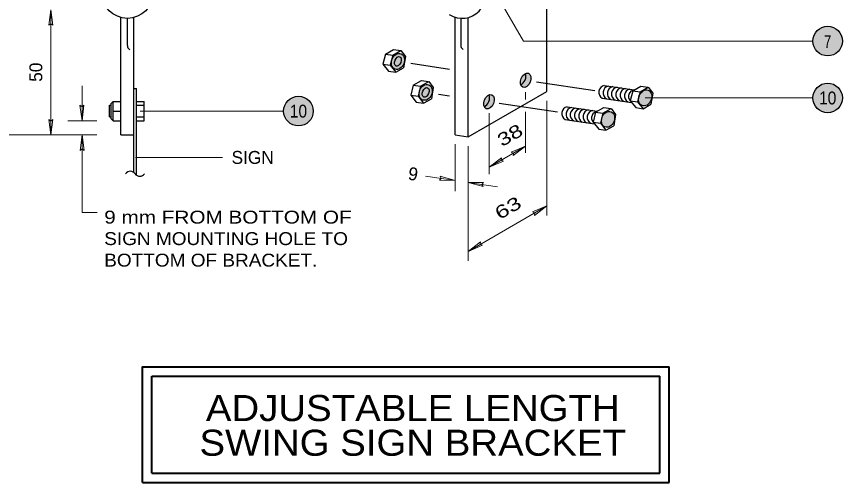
# Model space of a CAD drawing. Extents: x 312583 to 312853, y 144376 to 144586.
# Drawn here: x 312632.09 to 312680.07, y 144527.1 to 144554.18 of the extents above; entities that cross this region are included whole.
import ezdxf
from ezdxf.enums import TextEntityAlignment as Align

# ---------------------------------------------------------------- set-up
doc = ezdxf.new("R2010")
doc.units = 0
doc.header["$LTSCALE"] = 0.3
doc.layers.add('1', color=7, linetype='Continuous', lineweight=25)
doc.layers.add('2', color=7, linetype='Continuous', lineweight=13)

msp = doc.modelspace()

# ---------------------------------------------------------------- hatches: boundary and pattern name
at = {"layer": '1'}
h = msp.add_hatch(color=256, dxfattribs=at)
edge = h.paths.add_edge_path()
edge.add_ellipse((312654.2501, 144551.577), major_axis=(0.1805, 0.4441), ratio=0.761491, start_angle=0, end_angle=360)
h = msp.add_hatch(color=256, dxfattribs=at)
edge = h.paths.add_edge_path()
edge.add_ellipse((312654.2501, 144551.577), major_axis=(0.11, 0.2708), ratio=0.6087617, start_angle=0, end_angle=360)
h = msp.add_hatch(color=256, dxfattribs=at)
edge = h.paths.add_edge_path()
edge.add_ellipse((312661.6671, 144550.479), major_axis=(0.1639, 0.4034), ratio=0.649846, start_angle=0, end_angle=360)
h = msp.add_hatch(color=256, dxfattribs=at)
edge = h.paths.add_edge_path()
edge.add_ellipse((312655.8617, 144549.7761), major_axis=(0.1805, 0.4441), ratio=0.761491, start_angle=0, end_angle=360)
h = msp.add_hatch(color=256, dxfattribs=at)
edge = h.paths.add_edge_path()
edge.add_ellipse((312655.8617, 144549.7761), major_axis=(0.11, 0.2708), ratio=0.6087617, start_angle=0, end_angle=360)
h = msp.add_hatch(color=256, dxfattribs=at)
edge = h.paths.add_edge_path()
edge.add_ellipse((312668.6088, 144549.4512), major_axis=(0.1805, 0.4441), ratio=0.761491, start_angle=0, end_angle=360)
h = msp.add_hatch(color=256, dxfattribs=at)
edge = h.paths.add_edge_path()
edge.add_ellipse((312659.5421, 144549.2312), major_axis=(0.1639, 0.4034), ratio=0.649846, start_angle=0, end_angle=360)
h = msp.add_hatch(color=256, dxfattribs=at)
edge = h.paths.add_edge_path()
edge.add_ellipse((312666.4551, 144548.2077), major_axis=(0.1805, 0.4441), ratio=0.761491, start_angle=0, end_angle=360)
at = {"layer": '2'}
for points in [[(312680.0731, 144552.7571, 1), (312678.3539, 144552.7571, 1)], [(312680.0731, 144549.4512, 1), (312678.3539, 144549.4512, 1)], [(312649.3317, 144548.686, 1), (312647.6125, 144548.686, 1)]]:
    msp.add_hatch(color=256, dxfattribs=at).paths.add_polyline_path(points)

# ---------------------------------------------------------------- linework, layer by layer
at = {"layer": '1'}
for p, q in [((312662.8993, 144549.8312), (312662.8993, 144556.7218)), ((312638.1611, 144547.2985), (312638.1611, 144554.1257)), ((312638.5361, 144552.4902), (312638.5361, 144554.0781)), ((312638.9111, 144545.1146), (312638.9111, 144554.1257)), ((312657.5703, 144547.2985), (312657.5703, 144554.144)), ((312657.9001, 144554.0805), (312657.9001, 144552.5048)), ((312658.3203, 144547.1875), (312658.3203, 144554.1184)), ((312653.5298, 144551.9996), (312653.9992, 144552.2706)), ((312653.9992, 144552.2706), (312654.416, 144552.2089)), ((312653.5298, 144551.9996), (312653.3798, 144551.4131)), ((312653.3798, 144551.4131), (312653.8045, 144551.3502)), ((312654.1306, 144550.9496), (312654.5794, 144551.2087)), ((312654.9974, 144551.4663), (312657.2488, 144551.1331)), ((312655.1414, 144550.1987), (312654.9914, 144549.6122)), ((312655.1414, 144550.1987), (312655.6108, 144550.4697)), ((312655.6108, 144550.4697), (312656.0276, 144550.408)), ((312662.2931, 144550.3863), (312665.6791, 144549.8851)), ((312638.9111, 144549.9985), (312639.0611, 144549.9985)), ((312639.0611, 144544.9615), (312639.0611, 144549.9985)), ((312666.2395, 144550.1812), (312667.9755, 144549.9241)), ((312667.8885, 144549.8738), (312667.7385, 144549.2873)), ((312667.8885, 144549.8738), (312668.3579, 144550.1448)), ((312668.3579, 144550.1448), (312668.7747, 144550.0831)), ((312637.7111, 144549.2485), (312637.5986, 144549.136)), ((312637.7111, 144548.1235), (312637.7111, 144549.2485)), ((312637.7111, 144549.2485), (312638.1611, 144549.2485)), ((312639.0611, 144549.2485), (312639.5111, 144549.2485)), ((312639.5111, 144548.1235), (312639.5111, 144549.2485)), ((312654.9914, 144549.6122), (312655.4161, 144549.5493)), ((312655.7422, 144549.1487), (312656.191, 144549.4078)), ((312656.609, 144549.6654), (312657.2488, 144549.5707)), ((312666.1225, 144549.4403), (312667.8184, 144549.1891)), ((312667.7385, 144549.2873), (312668.1632, 144549.2244)), ((312637.4861, 144548.3485), (312637.4861, 144549.0235)), ((312637.4861, 144549.0235), (312637.5986, 144549.0235)), ((312637.5986, 144548.236), (312637.5986, 144549.136)), ((312639.0611, 144549.0235), (312639.5111, 144549.0235)), ((312660.1394, 144549.1429), (312663.5254, 144548.6417)), ((312664.0858, 144548.9377), (312665.8218, 144548.6806)), ((312665.7348, 144548.6304), (312666.2042, 144548.9014)), ((312666.2042, 144548.9014), (312666.621, 144548.8396)), ((312668.4893, 144548.8238), (312668.9381, 144549.0829)), ((312637.4861, 144548.3485), (312637.5986, 144548.3485)), ((312637.7111, 144548.686), (312638.1611, 144548.686)), ((312639.0611, 144548.3485), (312639.5111, 144548.3485)), ((312665.7348, 144548.6304), (312665.5848, 144548.0438)), ((312637.7111, 144548.1235), (312637.5986, 144548.236)), ((312637.7111, 144548.1235), (312638.1611, 144548.1235)), ((312639.0611, 144548.1235), (312639.5111, 144548.1235)), ((312663.9688, 144548.1968), (312665.6647, 144547.9456)), ((312665.5848, 144548.0438), (312666.0095, 144547.9809)), ((312666.3356, 144547.5803), (312666.7844, 144547.8395)), ((312638.1611, 144547.2985), (312638.9111, 144547.2985))]:
    msp.add_line(p, q, dxfattribs=at)
for points in [[(312653.5298, 144551.9996), (312653.9545, 144551.9368), (312654.4238, 144552.2077)], [(312654.4238, 144552.2077), (312654.6889, 144551.8608), (312654.5794, 144551.2087)], [(312653.9545, 144551.9368), (312653.8045, 144551.3502), (312654.1306, 144550.9496)], [(312653.3798, 144551.4131), (312653.7059, 144551.0125), (312654.1306, 144550.9496)], [(312655.1414, 144550.1987), (312655.5661, 144550.1359), (312656.0354, 144550.4068)], [(312656.0354, 144550.4068), (312656.3005, 144550.0599), (312656.191, 144549.4078)], [(312655.5661, 144550.1359), (312655.4161, 144549.5493), (312655.7422, 144549.1487)], [(312657.5703, 144547.2985), (312658.3203, 144547.1875), (312662.8993, 144549.8312)], [(312667.8885, 144549.8738), (312668.3132, 144549.811), (312668.7825, 144550.0819)], [(312668.3132, 144549.811), (312668.1632, 144549.2244), (312668.4893, 144548.8238)], [(312668.7825, 144550.0819), (312669.0476, 144549.735), (312668.9381, 144549.0829)], [(312654.9914, 144549.6122), (312655.3175, 144549.2116), (312655.7422, 144549.1487)], [(312667.7385, 144549.2873), (312668.0646, 144548.8867), (312668.4893, 144548.8238)], [(312665.7348, 144548.6304), (312666.1595, 144548.5675), (312666.6288, 144548.8385)], [(312666.6288, 144548.8385), (312666.8939, 144548.4916), (312666.7844, 144547.8395)], [(312666.1595, 144548.5675), (312666.0095, 144547.9809), (312666.3356, 144547.5803)], [(312665.5848, 144548.0438), (312665.9109, 144547.6432), (312666.3356, 144547.5803)]]:
    msp.add_lwpolyline(points, dxfattribs=at)
at = {"layer": '1', "lineweight": 13}
for points in [[(312660.8328, 144546.2971), (312661.6672, 144546.6518), (312660.9478, 144546.0979), (312660.9657, 144546.2468)], [(312660.3766, 144545.7796), (312659.5422, 144545.4249), (312660.2616, 144545.9788), (312660.2437, 144545.8299)], [(312656.6961, 144544.8953), (312657.5703, 144544.6547), (312656.6624, 144544.6677), (312656.769, 144544.7733)], [(312659.1945, 144544.3032), (312658.3203, 144544.5438), (312659.2282, 144544.5308), (312659.1216, 144544.4252)], [(312662.0649, 144542.8227), (312662.8993, 144543.1775), (312662.1799, 144542.6236), (312662.1978, 144542.7725)], [(312659.1547, 144540.8885), (312658.3203, 144540.5337), (312659.0397, 144541.0876), (312659.0218, 144540.9387)]]:
    msp.add_lwpolyline(points, close=True, dxfattribs=at)
at = {"layer": '1'}
msp.add_circle((312638.536, 144555.5781), 1.5, dxfattribs=at)
for centre, radius, start, end in [((312666.3144, 144549.7896), 0.3986, 100.84228, 241.21763), ((312666.5617, 144549.753), 0.3986, 100.84228, 241.21763), ((312666.809, 144549.7164), 0.3986, 100.84228, 241.21763), ((312667.0563, 144549.6798), 0.3986, 100.84228, 241.21763), ((312667.3036, 144549.6432), 0.3986, 100.84228, 241.21763), ((312667.5509, 144549.6065), 0.3986, 100.84228, 241.21763), ((312667.7982, 144549.5699), 0.3986, 100.84228, 241.21763), ((312668.0455, 144549.5333), 0.3986, 100.84228, 218.70473), ((312664.1607, 144548.5462), 0.3986, 100.84228, 241.21763), ((312664.408, 144548.5095), 0.3986, 100.84228, 241.21763), ((312664.6553, 144548.4729), 0.3986, 100.84228, 241.21763), ((312664.9026, 144548.4363), 0.3986, 100.84228, 241.21763), ((312665.1499, 144548.3997), 0.3986, 100.84228, 241.21763), ((312665.3972, 144548.3631), 0.3986, 100.84228, 241.21763), ((312665.6445, 144548.3265), 0.3986, 100.84228, 241.21763), ((312665.8968, 144548.2891), 0.3986, 100.84228, 218.17149), ((312638.7038, 144544.8548), 0.3323, 33.87567, 144.14149), ((312639.2536, 144545.2423), 0.3405, 216.4613, 322.83048)]:
    msp.add_arc(centre, radius, start, end, dxfattribs=at)
for centre, major_axis, ratio, start_param, end_param in [((312657.9148, 144555.5845), (-0.5733, 1.4109), 0.924918, 2.2297812, 7.5167148), ((312638.9697, 144552.4505), (0.4336, -0.0397), 0.649846, 3.1416763, 4.0446223), ((312658.3337, 144552.4651), (0.4336, -0.0397), 0.649846, 3.1416763, 4.0446223), ((312661.3802, 144550.6166), (0.1639, 0.4034), 0.649846, 3.6987557, 5.6461557), ((312659.2649, 144549.3422), (0.1639, 0.4034), 0.649846, 3.701042, 5.7298077)]:
    msp.add_ellipse(centre, major_axis=major_axis, ratio=ratio, start_param=start_param, end_param=end_param, dxfattribs=at)
for centre, major_axis, ratio in [((312654.2501, 144551.577), (0.1805, 0.4441), 0.761491), ((312654.2501, 144551.577), (0.11, 0.2708), 0.608762), ((312661.6671, 144550.479), (0.1639, 0.4034), 0.649846), ((312655.8617, 144549.7761), (0.1805, 0.4441), 0.761491), ((312655.8617, 144549.7761), (0.11, 0.2708), 0.608762), ((312668.6088, 144549.4512), (0.1805, 0.4441), 0.761491), ((312659.5421, 144549.2312), (0.1639, 0.4034), 0.649846), ((312666.4551, 144548.2077), (0.1805, 0.4441), 0.761491)]:
    msp.add_ellipse(centre, major_axis=major_axis, ratio=ratio, dxfattribs=at)
at = {"layer": '2'}
for p, q in [((312660.0162, 144555.3804), (312661.5504, 144552.7571)), ((312634.0907, 144547.2985), (312634.0907, 144554.5781)), ((312661.5504, 144552.7571), (312678.3539, 144552.7571)), ((312635.8985, 144550.156), (312635.8985, 144548.1235)), ((312661.6672, 144549.3621), (312661.6672, 144549.7887)), ((312662.8993, 144542.624), (312662.8993, 144549.2894)), ((312668.6088, 144549.4512), (312678.3539, 144549.4512)), ((312639.2861, 144548.686), (312647.6125, 144548.686)), ((312659.5422, 144545.0294), (312659.5422, 144548.5618)), ((312661.6672, 144546.2563), (312661.6672, 144548.6523)), ((312635.0749, 144548.1235), (312636.7664, 144548.1235)), ((312630.178, 144547.2985), (312636.7664, 144547.2985)), ((312635.8985, 144547.2985), (312635.8985, 144542.7866)), ((312657.5703, 144544.0328), (312657.5703, 144546.7567)), ((312658.3203, 144539.9802), (312658.3203, 144546.6457)), ((312659.5422, 144545.4249), (312661.6672, 144546.6518)), ((312638.9978, 144545.9891), (312644.0624, 144545.9891)), ((312655.8596, 144544.9078), (312657.5703, 144544.6547)), ((312658.3203, 144544.5438), (312660.031, 144544.2907)), ((312658.3203, 144540.5337), (312662.8993, 144543.1775)), ((312635.8985, 144542.7866), (312636.7721, 144542.7866))]:
    msp.add_line(p, q, dxfattribs=at)
at = {"layer": '2', "lineweight": 40}
for p, q in [((312670.0055, 144527.1003), (312670.0055, 144533.8181)), ((312639.9598, 144527.6393), (312639.9598, 144533.2791)), ((312639.9598, 144533.2791), (312669.4598, 144533.2791)), ((312669.4598, 144527.6393), (312669.4598, 144533.2791)), ((312639.9598, 144527.6393), (312669.4598, 144527.6393)), ((312639.4209, 144527.1003), (312670.0055, 144527.1003))]:
    msp.add_line(p, q, dxfattribs=at)
at = {"layer": '2'}
for points in [[(312633.9807, 144553.6781), (312634.0907, 144554.5781), (312634.2107, 144553.6781), (312634.0907, 144553.7681)], [(312636.0085, 144549.0235), (312635.8985, 144548.1235), (312635.7785, 144549.0235), (312635.8985, 144548.9335)], [(312634.2007, 144548.1985), (312634.0907, 144547.2985), (312633.9707, 144548.1985), (312634.0907, 144548.1085)], [(312635.7885, 144546.3985), (312635.8985, 144547.2985), (312636.0185, 144546.3985), (312635.8985, 144546.4885)]]:
    msp.add_lwpolyline(points, close=True, dxfattribs=at)
at = {"layer": '2', "lineweight": 40}
msp.add_lwpolyline([(312639.4209, 144527.1003), (312639.4209, 144533.8181), (312670.0055, 144533.8181)], dxfattribs=at)
at = {"layer": '2', "lineweight": 25}
for centre in [(312679.2135, 144552.7571), (312679.2135, 144549.4512), (312648.4721, 144548.686)]:
    msp.add_circle(centre, 0.8596, dxfattribs=at)

# ---------------------------------------------------------------- texts
at = {"layer": '2'}
for s, height, width, p in [('7', 0.75, 0.75, (312679.2135, 144552.3502)), ('10', 0.75, 0.9, (312679.2135, 144549.0762)), ('10', 0.75, 0.9, (312648.4721, 144548.311)), ('ADJUSTABLE LENGTH', 1.516, 1.1, (312655.1114, 144530.6695)), ('SWING SIGN BRACKET', 1.516, 1.1, (312655.1114, 144528.6533))]:
    msp.add_text(s, height=height, dxfattribs=dict(at, width=width)).set_placement(p, align=Align.CENTER)
for s, rotation, p in [('50', 90, (312633.5907, 144550.3898)), ('9', 351.584, (312654.8027, 144544.7061))]:
    msp.add_text(s, height=0.75, rotation=rotation, dxfattribs=at).set_placement(p)
for s, width, p in [('38', 1.35, (312660.292, 144546.5886)), ('63', 1.4, (312660.1553, 144542.3508))]:
    msp.add_text(s, height=0.75, rotation=30, dxfattribs=dict(at, width=width)).set_placement(p)
msp.add_text('SIGN', height=0.75, dxfattribs=at).set_placement((312644.5859, 144545.62))
for s, width, p in [('9 mm FROM BOTTOM OF', 1.2, (312637.1885, 144542.149)), ('SIGN MOUNTING HOLE TO', 1.1, (312637.1885, 144540.899)), ('BOTTOM OF BRACKET.', 1.1, (312637.1885, 144539.649))]:
    msp.add_text(s, height=0.75, dxfattribs=dict(at, width=width)).set_placement(p)

doc.saveas('drawing.dxf')
